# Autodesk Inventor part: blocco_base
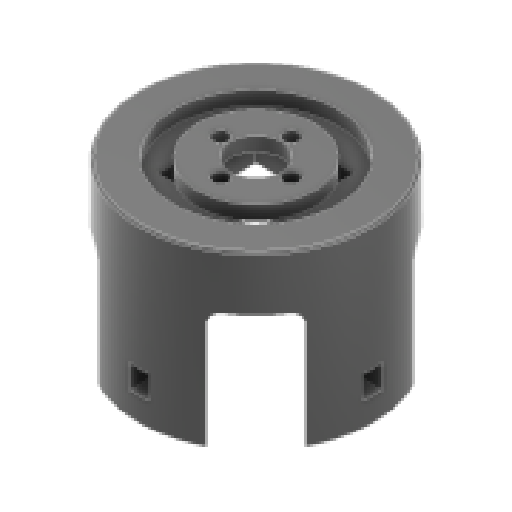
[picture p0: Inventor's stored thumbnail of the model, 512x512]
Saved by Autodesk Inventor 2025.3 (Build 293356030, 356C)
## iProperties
Created: 2026-03
Part Number: blocco_base
Material: Plastica ABS
Document SubType Name: Modeling
Designer: R5800u
Density: 1.06 g/cm^3
Appearance: Liscia - Nero
Author: R5800u
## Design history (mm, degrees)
sketch "Schizzo1"
  geometry: L1 (21, -21)-(-21, -21); L2 (-21, -21)-(-21, 21); L3 (-21, 21)-(21, 21); L4 (21, 21)-(21, -21); L5 (21, -21)-(-21, 21); L6 (-21, -21)-(21, 21); C1 r 50 at (0, 0); 1 further point
  constraints: 12 end point, 2 midpoint, 2 parallel, 1 centre point, 1 coincident, 1 horizontal, 1 perpendicular
  dimensions: "d0" = 100 diameter of C1; "d1" = 42 distance of L2.end L3.end; "d2" = 42 distance of L1.end L2.end
extrude "Estrusione1" new body sketch "Schizzo1" distance "d3" = 67.2; taper "d4" = 0 deg
sketch "Schizzo2"
  geometry: L1 (-21, 21)-(21, 21) reference; L2 (21, 21)-(21, -21) reference; L3 (21, -21)-(-21, -21) reference; L4 (-21, -21)-(-21, 21) reference; C1 r 35 at (0, 0); C2 r 50 at (0, 0) reference; C3 r 50 at (0, 0) reference; C4 r 25 at (0, 0); C5 r 11.1 at (0, 0); 1 further point
  constraints: 3 centre point, 3 coincident
  dimensions: "d5" = 70 diameter of C1; "d8" = 50 diameter of C4; "d9" = 22.2 diameter of C5
extrude "Estrusione2" join sketch "Schizzo2" distance "d6" = 8; taper "d7" = 0 deg
sketch "Schizzo3"
  geometry: C1 r 1.621 at (0, -15) reference; C2 r 1.621 at (-15, 0) reference; C3 r 1.621 at (15, 0) reference; C4 r 1.621 at (0, 15) reference; 1 further point
hole "Foro1" sketch "Schizzo3" at (-15, 0), (0, -15), (15, 0), (0, 15) diameter "d10" = 4.5; stored, may be unused: countersink angle "d14" = 82 deg, drill point angle "d16" = 118 deg; dims "d11" = 8, "d12" = 6.5, "d13" = 4.6, "d15" = 11.8
node "Piano di lavoro1"
sketch "Schizzo4"
  geometry: L1 (45.464, 2)-(46.619, 0) reference; L2 (44.309, 4)-(45.464, 2) reference; L3 (42, 4)-(44.309, 4) reference; L4 (46.619, 0)-(45.464, -2) reference; L5 (45.464, -2)-(44.309, -4) reference; L6 (44.309, -4)-(42, -4) reference; L7 (42, -4)-(39.691, -4) reference; L8 (39.691, -4)-(38.536, -2) reference; L9 (38.536, -2)-(37.381, 0) reference; L10 (37.381, 0)-(38.536, 2) reference; L11 (38.536, 2)-(39.691, 4) reference; L12 (39.691, 4)-(42, 4) reference; L13 (44.309, 4)-(49.84, 4); L14 (44.309, -4)-(49.84, -4); A1 r 50 centre (0, 0) between (49.84, 4) and (49.84, -4) reference; A2 r 50 centre (0, 0) between (49.84, 4) and (49.84, -4) reference
  constraints: 4 end point, 2 point on circle, 1 horizontal, 1 parallel
extrude "Estrusione3" cut sketch "Schizzo4" distance "d18" = 10; taper "d19" = 0 deg
sketch "Schizzo5"
  geometry: C1 r 2.65 at (65, 0) reference; 1 further point
extrude "Estrusione4" cut sketch "Schizzo5" distance "d20" = 25; taper "d21" = 0 deg
pattern_circular "Serie circolare1" dims "d23" = 360 deg
node "Piano di lavoro2"
sketch "Schizzo6"
  geometry: L1 (-50, -15)-(50, -15); L2 (50, -15)-(50, 15); L3 (50, 15)-(-50, 15); L4 (-50, 15)-(-50, -15); L5 (-50, -15)-(50, 15); L6 (50, -15)-(-50, 15); 1 further point
  constraints: 12 end point, 2 midpoint, 2 parallel, 1 horizontal, 1 perpendicular
  dimensions: "d26" = 100 distance of L3.end L2.end; "d27" = 30 distance of L2.end L1.end
extrude "Estrusione5" cut sketch "Schizzo6" extent not by distance; stored distance "d28" = 0; taper "d29" = 0 deg
pattern_circular "Serie circolare2" dims angle "d31" = 360 deg
fillet "Raccordo1" dims "d33" = 5
fillet "Raccordo2" dims "d34" = 1
node "Solido1"
node "Linea chiusa proiettata1"
node "Riferimento1"
node "Riferimento2"
node "Riferimento3"
node "Riferimento4"
node "Riferimento12"
node "Riferimento13"
node "Riferimento14"
node "Riferimento15"
node "Riferimento16"
node "Riferimento17"
node "Riferimento18"
node "Riferimento19"
node "Riferimento20"
node "Riferimento21"
node "Riferimento22"
node "Riferimento23"
node "Riferimento24"
other parameters: "d25" = 45 deg
